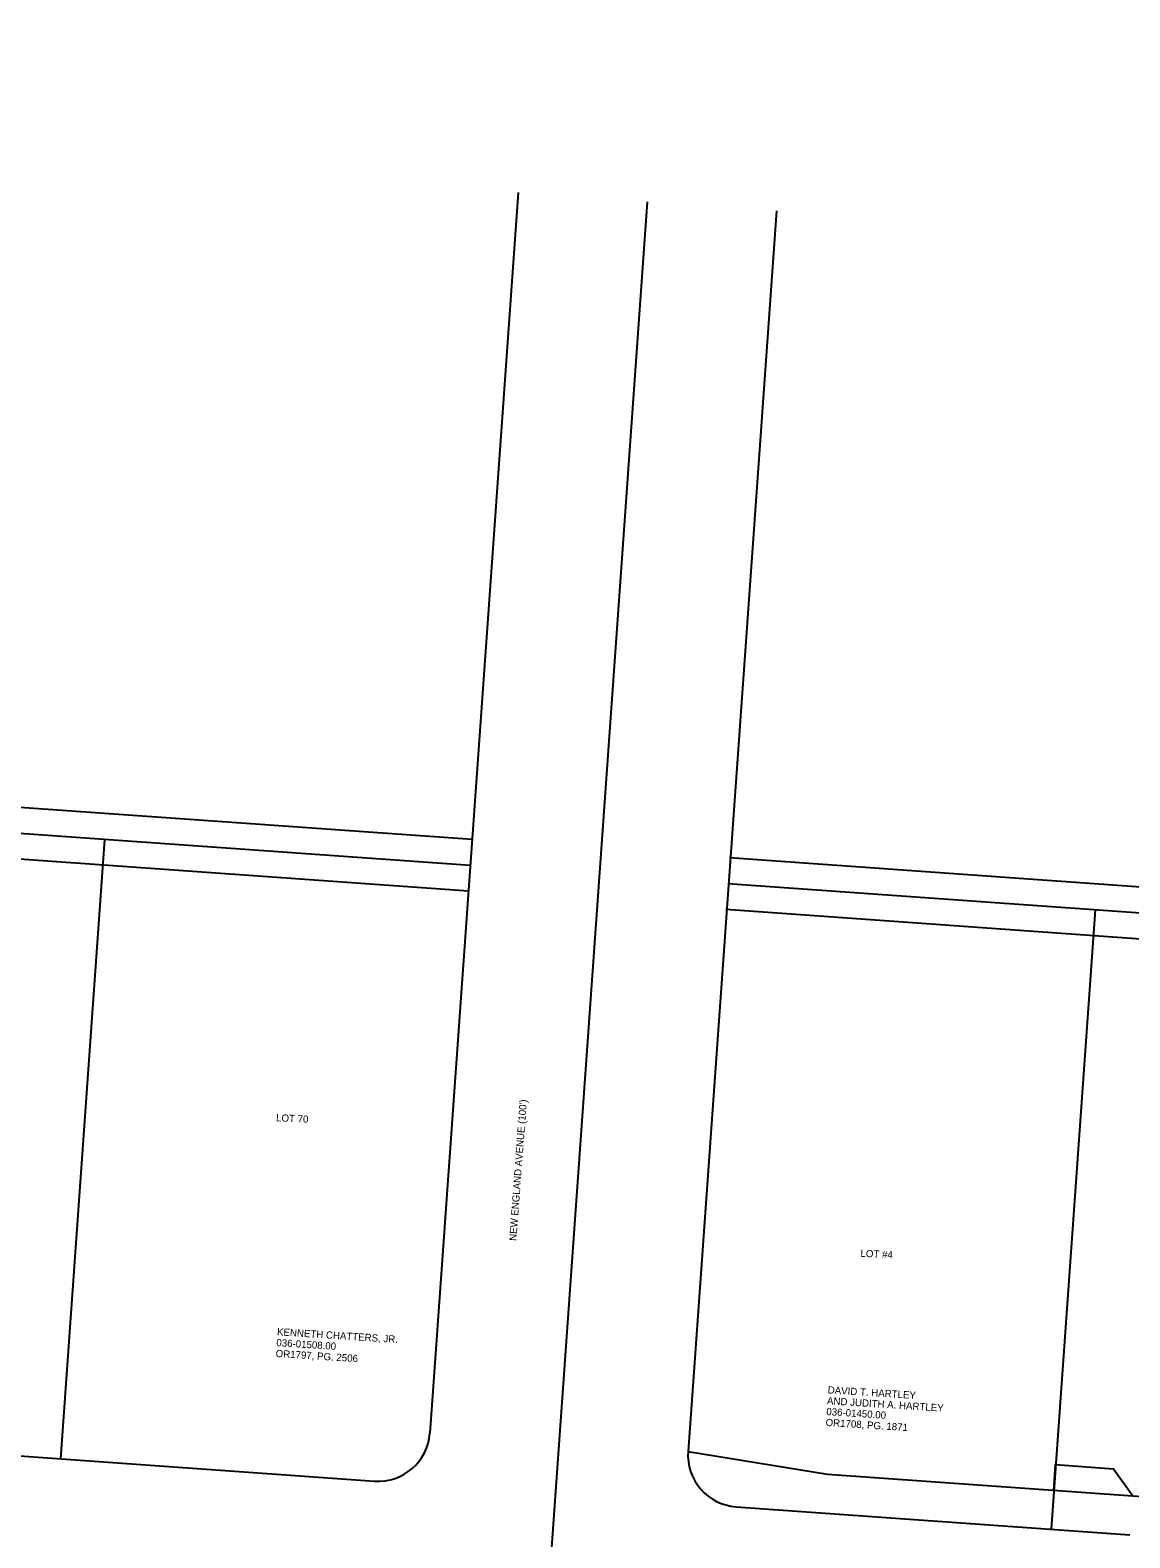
# Model space of a CAD drawing. Extents: x 1898254 to 1901377, y 701554 to 704886.
# Drawn here: x 1899393 to 1899818, y 703259 to 703841 of the extents above; entities that cross this region are included whole.
import ezdxf

# ---------------------------------------------------------------- set-up
doc = ezdxf.new("R2010")
doc.units = 0
for name, color, linetype in [('DV_X_Property_Line', 7, 'Continuous'), ('DV_X_Text', 7, 'Continuous'), ('RW_X_CL', 7, 'Continuous'), ('RW_X_Esmt_U', 7, 'Continuous'), ('RW_X_Fee_RW', 7, 'Continuous'), ('SC_Scratch2', 7, 'Continuous'), ('SV_P_Mon_Cells_Set', 7, 'Continuous'), ('VG_P_Cells', 7, 'Continuous')]:
    doc.layers.add(name, color=color, linetype=linetype)

msp = doc.modelspace()

# ---------------------------------------------------------------- linework, layer by layer
at = {"layer": 'DV_X_Property_Line'}
for p, q in [((1899563.1, 703518.49), (1898995.75, 703558.83)), ((1899421.78, 703528.54), (1899404.75, 703289.14)), ((1900230.14, 703471.05), (1899662.55, 703511.42)), ((1899804.49, 703501.32), (1899787.47, 703261.93))]:
    msp.add_line(p, q, dxfattribs=at)
at = {"layer": 'RW_X_CL'}
msp.add_line((1899631.47, 703775.05), (1899593.82, 703245.62), dxfattribs=at)
at = {"layer": 'RW_X_Esmt_U'}
for p, q in [((1899563.81, 703528.46), (1899188.39, 703555.16)), ((1899562.39, 703508.51), (1899174.08, 703536.13)), ((1900220.92, 703481.74), (1899663.26, 703521.39)), ((1900219.42, 703461.79), (1899661.84, 703501.44))]:
    msp.add_line(p, q, dxfattribs=at)
at = {"layer": 'RW_X_Fee_RW'}
for p, q in [((1899581.6, 703778.6), (1899547.5, 703299.04)), ((1899681.35, 703771.51), (1899647.24, 703291.95)), ((1898630.14, 703344.22), (1899526.13, 703280.51)), ((1899665.78, 703270.58), (1899817.89, 703259.76))]:
    msp.add_line(p, q, dxfattribs=at)
for centre, start, end in [((1899527.55, 703300.46), 265.93252, 355.93252), ((1899667.19, 703290.53), 175.93252, 265.93252)]:
    msp.add_arc(centre, 20, start, end, dxfattribs=at)
at = {"layer": 'SC_Scratch2'}
msp.add_circle((1899815.76, 703229.84), 1561.35, dxfattribs=at)
at = {"layer": 'SV_P_Mon_Cells_Set'}
msp.add_lwpolyline([(1899788.53, 703276.89), (1899789.24, 703286.86), (1899811.58, 703285.28), (1899819.04, 703274.72)], dxfattribs=at)
at = {"layer": 'VG_P_Cells'}
msp.add_lwpolyline([(1899647.24, 703291.95), (1899701.15, 703283.1), (1899819.04, 703274.72), (1899960.56, 703264.37), (1900071.43, 703251.26), (1900129.75, 703246.99), (1900212.52, 703235.93), (1900212.15, 703230.94)], dxfattribs=at)

# ---------------------------------------------------------------- texts
at = {"layer": 'DV_X_Text'}
for s, rotation, p in [("NEW ENGLAND AVENUE (100')", 85.7139, (1899580.89, 703373.26)), ('LOT 70', 357.09486, (1899488, 703419.6)), ('LOT #4', 357.09486, (1899713.79, 703367.21)), ('KENNETH CHATTERS, JR.', 356.3351, (1899488.35, 703336.86)), ('OR1797, PG. 2506', 356.3351, (1899487.82, 703328.48)), ('036-01508.00', 356.3351, (1899488.09, 703332.67)), ('DAVID T. HARTLEY ', 356.3351, (1899701.12, 703314.4)), ('036-01450.00', 356.3351, (1899700.58, 703306.02)), ('AND JUDITH A. HARTLEY', 356.3351, (1899700.85, 703310.21)), ('OR1708, PG. 1871', 356.3351, (1899700.31, 703301.83))]:
    msp.add_text(s, height=2.8, rotation=rotation, dxfattribs=at).set_placement(p)

doc.saveas('drawing.dxf')
